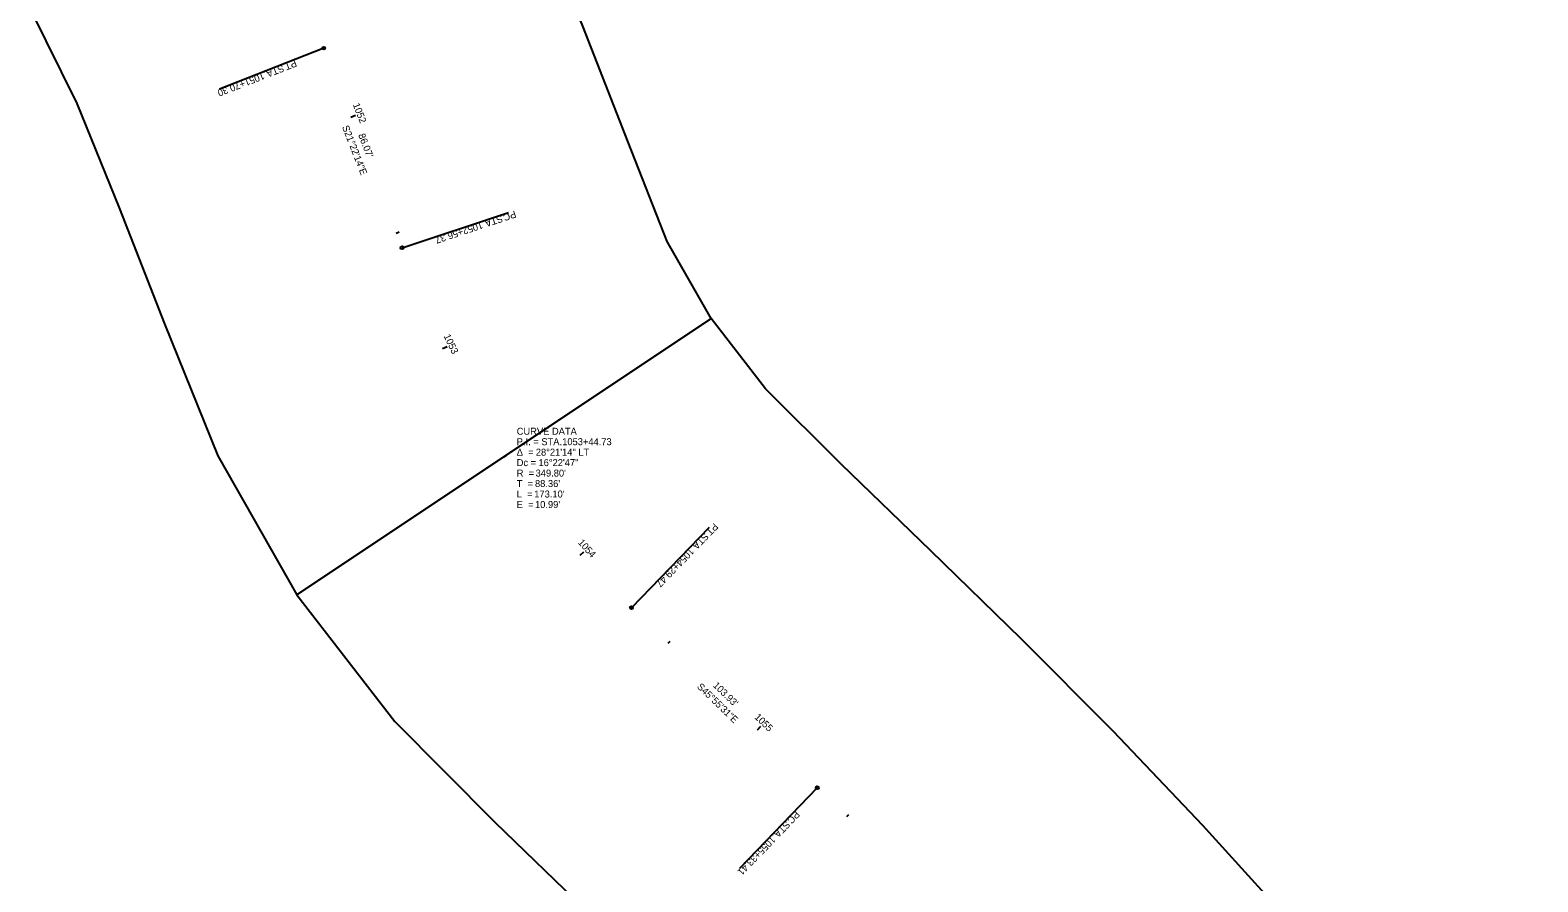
# Model space of a CAD drawing. Extents: x 1846275 to 1850613, y 577927 to 582526.
# Drawn here: x 1847531 to 1848136, y 580870 to 581212 of the extents above; entities that cross this region are included whole.
import ezdxf

# ---------------------------------------------------------------- set-up
doc = ezdxf.new("R2010")
doc.units = 0
for name, color, linetype in [('GE_P_Alignment_100_Cardinal_Points', 7, 'Continuous'), ('PM_P_Cells', 7, 'Continuous'), ('PM_P_Stop_Line', 7, 'Continuous'), ('PM_P_Transverse_Line', 7, 'Continuous'), ('SH_Named_Boundary', 7, 'Continuous'), ('XS_P_Pavt_Surface', 7, 'Continuous')]:
    doc.layers.add(name, color=color, linetype=linetype)

msp = doc.modelspace()

# ---------------------------------------------------------------- linework, layer by layer
at = {"layer": 'GE_P_Alignment_100_Cardinal_Points'}
for p, q in [((1847659.6, 581176.65), (1847661.46, 581177.38)), ((1847677.82, 581130.09), (1847678.93, 581130.53)), ((1847696.42, 581083.71), (1847698.22, 581084.57)), ((1847721.09, 581040.27), (1847722.09, 581040.93)), ((1847751.7, 581000.79), (1847753.19, 581002.12)), ((1847787.02, 580965.42), (1847787.86, 580966.28)), ((1847822.94, 580930.64), (1847824.33, 580932.08)), ((1847858.84, 580895.83), (1847859.68, 580896.69))]:
    msp.add_line(p, q, dxfattribs=at)
at = {"layer": 'PM_P_Cells'}
for p, q in [((1847648.77, 581204.31), (1847606.87, 581187.91)), ((1847680.14, 581124.16), (1847722.85, 581138.33)), ((1847772.28, 580979.7), (1847803.58, 581012.02)), ((1847846.94, 580907.4), (1847815.69, 580875.03))]:
    msp.add_line(p, q, dxfattribs=at)
for centre in [(1847648.77, 581204.31), (1847680.14, 581124.16), (1847772.28, 580979.7), (1847846.94, 580907.4)]:
    msp.add_circle(centre, 0.6, dxfattribs=at)
at = {"layer": 'SH_Named_Boundary'}
for points in [[(1847529.1, 581532.22), (1847391.79, 581386.81), (1847428.14, 581352.48), (1847457.8, 581323.55), (1847484.74, 581290.92), (1847509.1, 581256.32), (1847530.73, 581219.96), (1847549.51, 581182.04), (1847566.47, 581140.21), (1847584.69, 581093.64), (1847606.16, 581040.65), (1847637.89, 580984.79), (1847804.3, 581095.73), (1847786.68, 581126.76), (1847770.94, 581166.52), (1847752.72, 581213.09), (1847732.01, 581263.86), (1847706.42, 581315.54), (1847676.94, 581365.1), (1847643.74, 581412.25), (1847607.02, 581456.71), (1847565.46, 581497.89)], [(1847804.3, 581095.73), (1847637.89, 580984.79), (1847677.25, 580934.02), (1847717.47, 580893.57), (1847753.39, 580858.79), (1847788.83, 580824.42), (1847822.47, 580790.65), (1847855.33, 580756.11), (1847887.16, 580721.04), (1847920.21, 580683.53), (1847953.27, 580646.01), (1847986.32, 580608.49), (1848136.39, 580740.71), (1848103.33, 580778.23), (1848070.28, 580815.74), (1848037.22, 580853.26), (1848001.85, 580892.24), (1847965.79, 580930.16), (1847928.86, 580967.22), (1847892.51, 581002.48), (1847856.59, 581037.26), (1847826.16, 581067.54)]]:
    msp.add_lwpolyline(points, close=True, dxfattribs=at)

# ---------------------------------------------------------------- texts
at = {"layer": 'GE_P_Alignment_100_Cardinal_Points'}
for s, rotation, p in [('1052', 291.37063, (1847660.32, 581181.66)), ('1053', 295.49923, (1847696.79, 581088.75)), ('1054', 311.87883, (1847750.63, 581005.72)), ('1055', 315.92542, (1847821.51, 580935.51))]:
    msp.add_text(s, height=2.8, rotation=rotation, dxfattribs=at).set_placement(p)
at = {"layer": 'PM_P_Cells'}
for s, rotation, p in [(' STA. ', 201.37063, (1847633.06, 581198.11)), ('PT', 201.37063, (1847637.17, 581199.72)), ('1051+70.30', 201.37063, (1847624.26, 581194.67)), (' STA. ', 198.35271, (1847721.05, 581137.69)), ('PC', 198.35271, (1847725.4, 581139.13)), ('1052+56.37', 198.35271, (1847712.08, 581134.71)), (' STA. ', 225.92542, (1847802.34, 581010.69)), ('PT', 225.92542, (1847805.41, 581013.86)), ('1054+29.47', 225.92542, (1847795.77, 581003.9)), (' STA. ', 226.00405, (1847835.05, 580895.02)), ('PC', 226.00405, (1847838.23, 580898.32)), ('1055+33.41', 226.00405, (1847828.48, 580888.22))]:
    msp.add_text(s, height=2.8, rotation=rotation, dxfattribs=at).set_placement(p)
at = {"layer": 'PM_P_Stop_Line'}
for s, rotation, p in [('S21°22\'14"E', 291.37063, (1847656, 581172.67)), ('S45°55\'31"E', 315.92542, (1847798.41, 580947.71))]:
    msp.add_text(s, height=2.8, rotation=rotation, dxfattribs=at).set_placement(p)
at = {"layer": 'PM_P_Transverse_Line'}
for s, p in [('CURVE DATA', (1847726.21, 581049.13)), ('P.I. = STA. ', (1847726.21, 581044.93)), ('1053+44.73', (1847744.47, 581044.93)), ('Δ  = ', (1847726.21, 581040.73)), ('Dc = ', (1847726.21, 581036.53)), ('28°21\'14" LT', (1847733.88, 581040.73)), ('16°22\'47"', (1847734.95, 581036.53)), ('R  = ', (1847726.21, 581032.33)), ("349.80'", (1847733.79, 581032.33)), ('T  = ', (1847726.21, 581028.13)), ("88.36'", (1847733.54, 581028.13)), ('L  = ', (1847726.21, 581023.93)), ('E  = ', (1847726.21, 581019.73)), ("173.10'", (1847733.25, 581023.93)), ("10.99'", (1847733.55, 581019.73))]:
    msp.add_text(s, height=2.8, dxfattribs=at).set_placement(p)
at = {"layer": 'XS_P_Pavt_Surface'}
for s, rotation, p in [("86.07'", 291.37063, (1847662.47, 581169.43)), ("103.93'", 315.92542, (1847804.84, 580948.22))]:
    msp.add_text(s, height=2.8, rotation=rotation, dxfattribs=at).set_placement(p)

doc.saveas('drawing.dxf')
